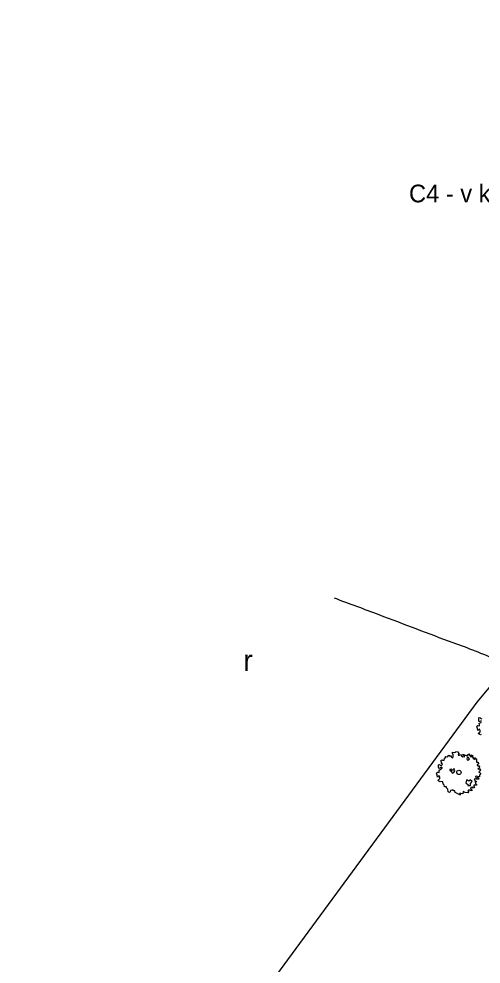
# Model space of a CAD drawing. Extents: x -477701 to -476785, y -1116511 to -1115314.
# Drawn here: x -477336.7 to -477284.5, y -1115532.3 to -1115425.7 of the extents above; entities that cross this region are included whole.
import ezdxf

# ---------------------------------------------------------------- set-up
doc = ezdxf.new("R2010")
doc.units = 0
for name, color, linetype in [('IP_RBK', 7, 'Continuous'), ('ObPÚ', 7, 'Continuous'), ('popis', 7, 'Continuous'), ('SVK_STAT', 7, 'Continuous'), ('Vrstevnice_vedlejsi', 7, 'Continuous')]:
    doc.layers.add(name, color=color, linetype=linetype)

msp = doc.modelspace()

# ---------------------------------------------------------------- linework, layer by layer
at = {"layer": 'IP_RBK'}
for points in [[(-477284.53, -1115506.43), (-477284.6, -1115506.47), (-477284.75, -1115506.41), (-477284.88, -1115506.33), (-477284.64, -1115506.12), (-477284.64, -1115505.96), (-477284.71, -1115505.81), (-477284.81, -1115505.85), (-477284.92, -1115505.98), (-477284.95, -1115505.74), (-477285.01, -1115505.49), (-477284.92, -1115505.41), (-477284.73, -1115505.45), (-477284.71, -1115505.32), (-477284.74, -1115505.17), (-477284.48, -1115505.04)], [(-477284.5, -1115504.91), (-477284.61, -1115504.91), (-477284.75, -1115504.99), (-477284.8, -1115504.82), (-477284.79, -1115504.56), (-477284.67, -1115504.52), (-477284.56, -1115504.64), (-477284.46, -1115504.68)]]:
    msp.add_lwpolyline(points, dxfattribs=at)
for points in [[(-477285.62, -1115508.74), (-477285.47, -1115508.85), (-477285.5, -1115508.98), (-477285.41, -1115509.16), (-477285.2, -1115509.25), (-477285.27, -1115509.08), (-477285.19, -1115509.06), (-477285.01, -1115509.25), (-477285.05, -1115509.24), (-477285.06, -1115509.54), (-477284.88, -1115509.56), (-477284.84, -1115509.69), (-477284.86, -1115509.8), (-477284.97, -1115509.83), (-477284.99, -1115509.9), (-477284.84, -1115510.05), (-477284.82, -1115509.93), (-477284.73, -1115510.07), (-477284.77, -1115510.21), (-477284.92, -1115510.26), (-477284.87, -1115510.35), (-477284.68, -1115510.31), (-477284.62, -1115510.4), (-477284.68, -1115510.54), (-477284.8, -1115510.65), (-477284.59, -1115510.78), (-477284.59, -1115510.9), (-477284.73, -1115511.03), (-477284.72, -1115511.19), (-477284.83, -1115511.21), (-477285.02, -1115511.12), (-477285.16, -1115511.17), (-477285.14, -1115511.33), (-477285, -1115511.41), (-477285.01, -1115511.33), (-477284.94, -1115511.29), (-477284.86, -1115511.27), (-477284.78, -1115511.42), (-477284.85, -1115511.51), (-477285.07, -1115511.48), (-477285.15, -1115511.43), (-477285.34, -1115511.46), (-477285.32, -1115511.47), (-477285.18, -1115511.72), (-477285.02, -1115511.74), (-477285.21, -1115511.86), (-477285.17, -1115511.98), (-477285.04, -1115512.04), (-477285.04, -1115512.13), (-477285.36, -1115512.15), (-477285.37, -1115512.31), (-477285.28, -1115512.39), (-477285.44, -1115512.48), (-477285.51, -1115512.38), (-477285.65, -1115512.41), (-477285.73, -1115512.54), (-477285.59, -1115512.68), (-477285.59, -1115512.77), (-477285.72, -1115512.75), (-477285.79, -1115512.7), (-477285.91, -1115512.71), (-477286.02, -1115512.79), (-477285.94, -1115512.95), (-477286.01, -1115513.01), (-477286.32, -1115512.98), (-477286.55, -1115512.86), (-477286.61, -1115513.13), (-477286.82, -1115513.07), (-477286.96, -1115513.09), (-477286.87, -1115513.26), (-477287.45, -1115512.96), (-477287.52, -1115512.8), (-477287.64, -1115512.79), (-477287.67, -1115512.72), (-477287.85, -1115512.71), (-477287.99, -1115512.74), (-477288.02, -1115512.9), (-477288.11, -1115512.97), (-477288.26, -1115512.89), (-477288.29, -1115512.6), (-477288.5, -1115512.4), (-477288.44, -1115512.29), (-477288.69, -1115512.33), (-477288.7, -1115512.09), (-477288.79, -1115512.06), (-477288.85, -1115511.84), (-477288.85, -1115511.78), (-477289.08, -1115511.72), (-477289.15, -1115511.76), (-477289.31, -1115511.7), (-477289.44, -1115511.62), (-477289.2, -1115511.41), (-477289.19, -1115511.24), (-477289.26, -1115511.1), (-477289.37, -1115511.14), (-477289.48, -1115511.26), (-477289.51, -1115511.02), (-477289.57, -1115510.78), (-477289.47, -1115510.69), (-477289.28, -1115510.73), (-477289.26, -1115510.61), (-477289.29, -1115510.46), (-477289.04, -1115510.32), (-477288.94, -1115510.21), (-477288.96, -1115510.12), (-477289.05, -1115510.19), (-477289.17, -1115510.19), (-477289.3, -1115510.28), (-477289.36, -1115510.1), (-477289.34, -1115509.85), (-477289.22, -1115509.8), (-477289.12, -1115509.92), (-477289.01, -1115509.96), (-477288.91, -1115509.75), (-477288.9, -1115509.72), (-477289.05, -1115509.71), (-477288.99, -1115509.6), (-477289.04, -1115509.52), (-477289.08, -1115509.39), (-477288.99, -1115509.29), (-477288.89, -1115509.33), (-477288.71, -1115509.32), (-477288.67, -1115509.18), (-477288.68, -1115509.09), (-477288.53, -1115509), (-477288.57, -1115508.91), (-477288.36, -1115508.95), (-477288.27, -1115508.9), (-477288.27, -1115508.8), (-477288.14, -1115508.75), (-477288.13, -1115508.82), (-477288.04, -1115508.82), (-477287.96, -1115508.84), (-477287.92, -1115508.88), (-477287.91, -1115508.95), (-477287.86, -1115509.01), (-477287.81, -1115509.05), (-477287.73, -1115509.03), (-477287.69, -1115508.93), (-477287.69, -1115508.71), (-477287.76, -1115508.54), (-477287.76, -1115508.43), (-477287.57, -1115508.46), (-477287.44, -1115508.42), (-477287.41, -1115508.34), (-477287.14, -1115508.4), (-477287.12, -1115508.47), (-477287.06, -1115508.56), (-477287.11, -1115508.76), (-477287.01, -1115508.77), (-477286.86, -1115508.68), (-477286.76, -1115508.84), (-477286.59, -1115508.95), (-477286.39, -1115508.91), (-477286.64, -1115508.68), (-477286.51, -1115508.67), (-477286.13, -1115508.85), (-477286.05, -1115508.71), (-477285.88, -1115508.61), (-477285.84, -1115508.63), (-477285.88, -1115508.74), (-477285.68, -1115508.94), (-477285.58, -1115508.9)], [(-477286.13, -1115509.03), (-477286.16, -1115509.18), (-477286.08, -1115509.33), (-477285.94, -1115509.28), (-477285.84, -1115509.18), (-477285.95, -1115509.04)], [(-477287.91, -1115510.47), (-477287.91, -1115510.61), (-477287.78, -1115510.81), (-477287.63, -1115510.72), (-477287.5, -1115510.54), (-477287.62, -1115510.28), (-477287.65, -1115510.46), (-477287.76, -1115510.44), (-477287.85, -1115510.37), (-477287.89, -1115510.34), (-477288.08, -1115510.36), (-477288.07, -1115510.45), (-477288.02, -1115510.53), (-477287.95, -1115510.5)], [(-477286.14, -1115511.55), (-477286.25, -1115511.88), (-477285.99, -1115512.12), (-477286.04, -1115512.17), (-477285.75, -1115512.18), (-477285.75, -1115511.96), (-477285.54, -1115511.74), (-477285.76, -1115511.53), (-477285.92, -1115511.7), (-477286.02, -1115511.6)]]:
    msp.add_lwpolyline(points, close=True, dxfattribs=at)
msp.add_circle((-477287.05, -1115510.71), 0.247, dxfattribs=at)
at = {"layer": 'ObPÚ'}
msp.add_lwpolyline([(-477353.12, -1115595.36), (-477284.99, -1115502.79), (-477206.42, -1115409.08), (-477145.49, -1115363.15), (-477127.14, -1115341.36)], dxfattribs=at)
at = {"layer": 'Vrstevnice_vedlejsi'}
msp.add_spline([(-477206.22, -1115569.64), (-477212.94, -1115565.91), (-477219.56, -1115561.19), (-477226.09, -1115555.47), (-477232.53, -1115548.76), (-477236.88, -1115544.21), (-477239.15, -1115541.82), (-477239.33, -1115541.61), (-477242.04, -1115539.68), (-477247.28, -1115536.05), (-477255.05, -1115530.7), (-477261.96, -1115524.55), (-477268.01, -1115517.59), (-477273.19, -1115509.81), (-477276.69, -1115504.54), (-477278.49, -1115501.78), (-477278.6, -1115501.51), (-477278.77, -1115501.18), (-477278.98, -1115500.77), (-477279.24, -1115500.29), (-477279.95, -1115499.68), (-477281.11, -1115498.95), (-477282.71, -1115498.09), (-477287.69, -1115496.09), (-477296.04, -1115492.94), (-477301.09, -1115491.06)], degree=3, dxfattribs=at)

# ---------------------------------------------------------------- texts
at = {"layer": 'popis'}
msp.add_text('C4 - v k.ú. Stará Ves nad Ondřejnicí', height=2, rotation=360, dxfattribs=at).set_placement((-477292.68, -1115446.39))
at = {"layer": 'SVK_STAT'}
msp.add_text('r', height=2.4, dxfattribs=at).set_placement((-477311.4, -1115499.28))

doc.saveas('drawing.dxf')
